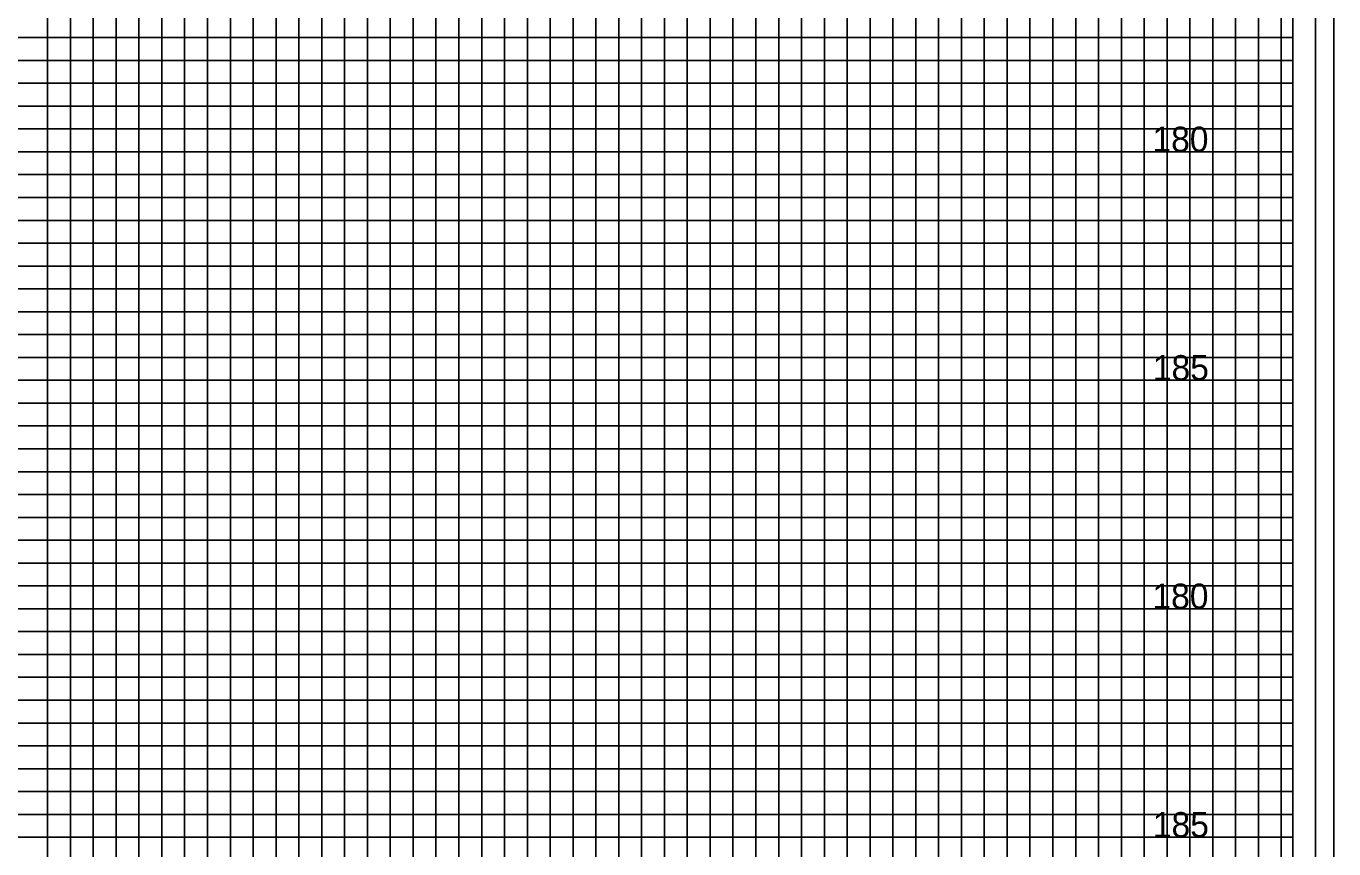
# Model space of a CAD drawing. Extents: x -4 to 103, y -2 to 209.
# Drawn here: x 74.78 to 103.4, y 173.9 to 191.9 of the extents above; entities that cross this region are included whole.
import ezdxf

# ---------------------------------------------------------------- set-up
doc = ezdxf.new("R2010")
doc.units = 0
for name, color, linetype in [('Old_Level_10', 7, 'Continuous'), ('Old_Level_4', 7, 'Continuous'), ('Old_Level_5', 7, 'Continuous'), ('Old_Level_6', 7, 'Continuous'), ('Old_Level_8', 7, 'Continuous'), ('Prop Dimension', 7, 'Continuous'), ('Prop XS Subgrade Earthwork', 7, 'Continuous')]:
    doc.layers.add(name, color=color, linetype=linetype)

msp = doc.modelspace()

# ---------------------------------------------------------------- linework, layer by layer
at = {"layer": 'Old_Level_10'}
for p, q in [((91.25, 141.65), (91.25, 205.075)), ((93.75, 141.65), (93.75, 205.075)), ((96.25, 141.65), (96.25, 205.075)), ((98.75, 141.65), (98.75, 205.075)), ((101.25, 141.65), (101.25, 205.075)), ((76.25, 141.65), (76.25, 203.65)), ((78.75, 141.65), (78.75, 203.65)), ((81.25, 141.65), (81.25, 203.65)), ((83.75, 141.65), (83.75, 203.65)), ((86.25, 141.65), (86.25, 203.65)), ((88.75, 141.65), (88.75, 203.65)), ((0, 191.65), (102.5, 191.65)), ((0, 189.15), (102.5, 189.15)), ((0, 186.65), (102.5, 186.65)), ((0, 184.15), (102.5, 184.15)), ((0, 181.65), (102.5, 181.65)), ((0, 179.15), (102.5, 179.15)), ((0, 176.65), (102.5, 176.65)), ((0, 174.15), (102.5, 174.15))]:
    msp.add_line(p, q, dxfattribs=at)
at = {"layer": 'Old_Level_4'}
msp.add_lwpolyline([(103, 207.65), (-2.8, 207.65), (-2.8, 140.65), (103, 140.65)], close=True, dxfattribs=at)
at = {"layer": 'Old_Level_5'}
msp.add_lwpolyline([(103.4, 209.05), (-3.5, 209.05), (-3.5, 139.225), (103.4, 139.225)], close=True, dxfattribs=at)
at = {"layer": 'Old_Level_6'}
msp.add_lwpolyline([(102.5, 206.65), (0, 206.65), (0, 141.65), (102.5, 141.65)], close=True, dxfattribs=at)
at = {"layer": 'Old_Level_8'}
for points in [[(91.25, 141.65), (91.25, 205.075), (93.75, 205.075), (93.75, 141.65)], [(96.25, 141.65), (96.25, 205.075), (98.75, 205.075), (98.75, 141.65)], [(101.25, 141.65), (101.25, 205.075)], [(76.25, 141.65), (76.25, 203.65), (78.75, 203.65), (78.75, 141.65)], [(81.25, 141.65), (81.25, 203.65), (83.75, 203.65), (83.75, 141.65)], [(86.25, 141.65), (86.25, 203.65), (88.75, 203.65), (88.75, 141.65)], [(0, 189.15), (102.5, 189.15), (102.5, 191.65), (0, 191.65)], [(0, 184.15), (102.5, 184.15), (102.5, 186.65), (0, 186.65)], [(0, 179.15), (102.5, 179.15), (102.5, 181.65), (0, 181.65)], [(0, 174.15), (102.5, 174.15), (102.5, 176.65), (0, 176.65)]]:
    msp.add_lwpolyline(points, dxfattribs=at)
at = {"layer": 'Prop Dimension'}
for points in [[(90.25, 141.65), (90.25, 205.075), (90.75, 205.075), (90.75, 141.65)], [(91.75, 141.65), (91.75, 205.075), (92.25, 205.075), (92.25, 141.65)], [(92.75, 141.65), (92.75, 205.075), (93.25, 205.075), (93.25, 141.65)], [(94.25, 141.65), (94.25, 205.075), (94.75, 205.075), (94.75, 141.65)], [(95.25, 141.65), (95.25, 205.075), (95.75, 205.075), (95.75, 141.65)], [(96.75, 141.65), (96.75, 205.075), (97.25, 205.075), (97.25, 141.65)], [(97.75, 141.65), (97.75, 205.075), (98.25, 205.075), (98.25, 141.65)], [(99.25, 141.65), (99.25, 205.075), (99.75, 205.075), (99.75, 141.65)], [(100.25, 141.65), (100.25, 205.075)], [(100.25, 205.075), (100.75, 205.075), (100.75, 141.65), (101.75, 141.65), (101.75, 205.075), (102.25, 205.075), (102.25, 141.65)], [(75.25, 141.65), (75.25, 203.65), (75.75, 203.65), (75.75, 141.65)], [(76.75, 141.65), (76.75, 203.65), (77.25, 203.65), (77.25, 141.65)], [(77.75, 141.65), (77.75, 203.65), (78.25, 203.65), (78.25, 141.65)], [(79.25, 141.65), (79.25, 203.65), (79.75, 203.65), (79.75, 141.65)], [(80.25, 141.65), (80.25, 203.65), (80.75, 203.65), (80.75, 141.65)], [(81.75, 141.65), (81.75, 203.65), (82.25, 203.65), (82.25, 141.65)], [(82.75, 141.65), (82.75, 203.65), (83.25, 203.65), (83.25, 141.65)], [(84.25, 141.65), (84.25, 203.65), (84.75, 203.65), (84.75, 141.65)], [(85.25, 141.65), (85.25, 203.65), (85.75, 203.65), (85.75, 141.65)], [(86.75, 141.65), (86.75, 203.65), (87.25, 203.65), (87.25, 141.65)], [(87.75, 141.65), (87.75, 203.65), (88.25, 203.65), (88.25, 141.65)], [(89.25, 141.65), (89.25, 203.65), (89.75, 203.65), (89.75, 141.65)], [(0, 190.65), (102.5, 190.65), (102.5, 191.15), (0, 191.15)], [(0, 189.65), (102.5, 189.65), (102.5, 190.15), (0, 190.15)], [(0, 188.15), (102.5, 188.15), (102.5, 188.65), (0, 188.65)], [(0, 187.15), (102.5, 187.15), (102.5, 187.65), (0, 187.65)], [(0, 185.65), (102.5, 185.65), (102.5, 186.15), (0, 186.15)], [(0, 184.65), (102.5, 184.65), (102.5, 185.15), (0, 185.15)], [(0, 183.15), (102.5, 183.15), (102.5, 183.65), (0, 183.65)], [(0, 182.15), (102.5, 182.15), (102.5, 182.65), (0, 182.65)], [(0, 180.65), (102.5, 180.65), (102.5, 181.15), (0, 181.15)], [(0, 179.65), (102.5, 179.65), (102.5, 180.15), (0, 180.15)], [(0, 178.15), (102.5, 178.15), (102.5, 178.65), (0, 178.65)], [(0, 177.15), (102.5, 177.15), (102.5, 177.65), (0, 177.65)], [(0, 175.65), (102.5, 175.65), (102.5, 176.15), (0, 176.15)], [(0, 174.65), (102.5, 174.65), (102.5, 175.15), (0, 175.15)]]:
    msp.add_lwpolyline(points, dxfattribs=at)

# ---------------------------------------------------------------- texts
at = {"layer": 'Prop XS Subgrade Earthwork'}
for s, p in [('180', (99.4296, 189.15)), ('185', (99.4383, 184.15)), ('180', (99.4296, 179.15)), ('185', (99.4383, 174.15))]:
    msp.add_text(s, height=0.55, dxfattribs=at).set_placement(p)

doc.saveas('drawing.dxf')
